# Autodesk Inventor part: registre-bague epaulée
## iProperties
Author: chr
Created: 2001-06
Part Number: registre-bague epaulée
Material: Par défaut
Document SubType Name: Modélisation
Designer: chr
Control State: 0
Master: False
Checked Out: False
PropertySet Name: Design Tracking Control
Shininess: 20.0
PropertySet Name: _Private Model Information
Length Units: 11269
Angle Units: 11286
Time Units: 11279
Mass Units: 11290
Length Display Precision: 3
Angle Display Precision: 2
Compacted: False
Density: 0.0
Volumn: 0.0
Area: 0.0
PropertySet Name: Model Information
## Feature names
1. Extrusion1
2. Extrusion2
3. Extrusion3
